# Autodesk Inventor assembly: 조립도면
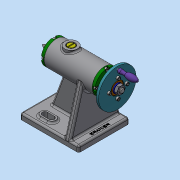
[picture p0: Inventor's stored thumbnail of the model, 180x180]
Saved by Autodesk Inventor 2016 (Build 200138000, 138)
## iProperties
Created: 2019-10
Part Number: 조립도면
Document SubType Name: Assembly
Designer: MIRAE
Author: MIRAE
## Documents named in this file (18)
- C:\Users\MIRAE\Desktop\491004V1016\조립도면.iam
- C:\Users\MIRAE\Desktop\491004V1016\본체.ipt
- C:\Users\MIRAE\Desktop\491004V1016\슬리브.ipt
- C:\Users\MIRAE\Desktop\491004V1016\중공축.ipt
- C:\Users\MIRAE\Desktop\491004V1016\센터홀더.ipt
- C:\Users\MIRAE\Desktop\491004V1016\멈춤나사 M3.ipt
- C:\Users\MIRAE\Desktop\491004V1016\센터.ipt
- C:\Users\MIRAE\Desktop\491004V1016\커버.ipt
- C:\Users\MIRAE\Desktop\491004V1016\부시.ipt
- C:\Users\MIRAE\Desktop\491004V1016\나사축.ipt
- C:\Users\MIRAE\Desktop\491004V1016\키 4 x 4 x 10.ipt
- C:\Users\MIRAE\Desktop\491004V1016\플랜지.ipt
- C:\Users\MIRAE\Desktop\491004V1016\돌림판.ipt
- C:\Users\MIRAE\Desktop\491004V1016\볼트 M3.ipt
- C:\Users\MIRAE\Desktop\491004V1016\와셔.ipt
- C:\Users\MIRAE\Desktop\491004V1016\너트 M8.ipt
- C:\Users\MIRAE\Desktop\491004V1016\핸들.ipt
- C:\Users\MIRAE\Desktop\491004V1016\나사.ipt
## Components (2 placed, 2 different names)
1. 플랜지:1
2. 핸들:1
